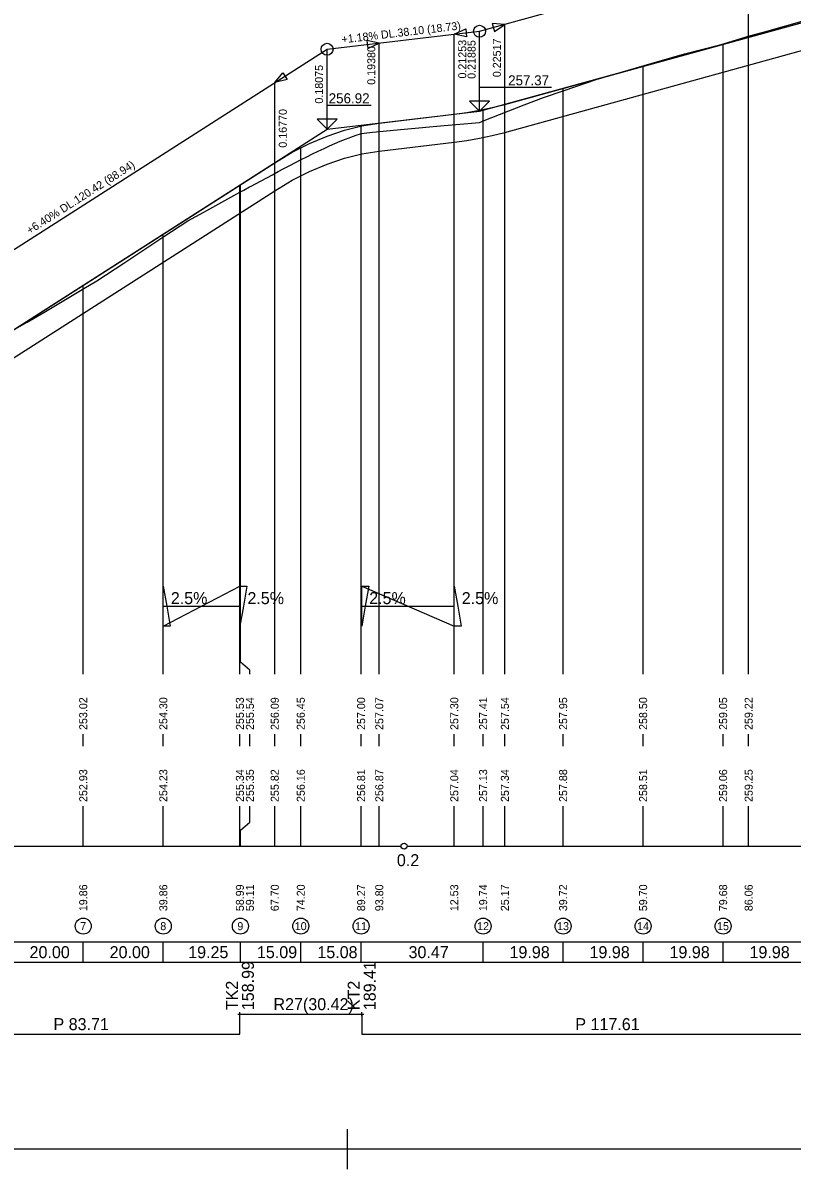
# Model space of a CAD drawing. Extents: x -5 to 681, y -26 to 404.
# Drawn here: x 174.8 to 366.9, y -25.7 to 260.8 of the extents above; entities that cross this region are included whole.
import ezdxf

# ---------------------------------------------------------------- set-up
doc = ezdxf.new("R2010")
doc.units = 0
for name, color, linetype in [('KOTA', 7, 'Continuous'), ('NOVY_STAV', 7, 'Continuous'), ('NS_OBLOUK', 7, 'Continuous'), ('PRIKOPY', 7, 'Continuous'), ('REZY_PO', 7, 'Continuous'), ('SESTAVY_REZU_PO', 7, 'Continuous'), ('SKLONOVE_POMERY', 7, 'Continuous'), ('SKLONOVE_POMERY_PROPOJENI', 7, 'Continuous'), ('SMEROVE_POMERY', 7, 'Continuous'), ('SMEROVE_POMERY_KOD', 7, 'Continuous'), ('SVK_STAT', 7, 'Continuous'), ('TABULKY', 7, 'Continuous'), ('ZNACKY', 7, 'Continuous')]:
    doc.layers.add(name, color=color, linetype=linetype)

msp = doc.modelspace()

# ---------------------------------------------------------------- linework, layer by layer
for p, q in [((255.78, -15.73), (255.78, -25.73)), ((255.78, -15.73), (255.78, -25.73)), ((255.78, -15.73), (255.78, -25.73)), ((255.78, -15.73), (255.78, -25.73)), ((255.78, -15.73), (255.78, -25.73)), ((255.78, -15.73), (255.78, -25.73)), ((255.78, -15.73), (255.78, -25.73)), ((255.78, -15.73), (255.78, -25.73)), ((255.78, -15.73), (255.78, -25.73)), ((255.78, -15.73), (255.78, -25.73)), ((255.78, -15.73), (255.78, -25.73)), ((255.78, -15.73), (255.78, -25.73)), ((255.78, -15.73), (255.78, -25.73)), ((255.78, -15.73), (255.78, -25.73)), ((255.78, -15.73), (255.78, -25.73)), ((255.78, -15.73), (255.78, -25.73)), ((255.78, -15.73), (255.78, -25.73)), ((255.78, -15.73), (255.78, -25.73)), ((255.78, -15.73), (255.78, -25.73)), ((255.78, -15.73), (255.78, -25.73)), ((260.78, -20.73), (250.78, -20.73)), ((260.78, -20.73), (250.78, -20.73)), ((260.78, -20.73), (250.78, -20.73)), ((260.78, -20.73), (250.78, -20.73)), ((260.78, -20.73), (250.78, -20.73)), ((260.78, -20.73), (250.78, -20.73)), ((260.78, -20.73), (250.78, -20.73)), ((260.78, -20.73), (250.78, -20.73)), ((260.78, -20.73), (250.78, -20.73)), ((260.78, -20.73), (250.78, -20.73)), ((260.78, -20.73), (250.78, -20.73)), ((260.78, -20.73), (250.78, -20.73)), ((260.78, -20.73), (250.78, -20.73)), ((260.78, -20.73), (250.78, -20.73)), ((260.78, -20.73), (250.78, -20.73)), ((260.78, -20.73), (250.78, -20.73)), ((260.78, -20.73), (250.78, -20.73)), ((260.78, -20.73), (250.78, -20.73)), ((260.78, -20.73), (250.78, -20.73)), ((260.78, -20.73), (250.78, -20.73))]:
    msp.add_line(p, q)
msp.add_lwpolyline([(675.78, -20.77), (0.45, -20.77), (0.45, 399.23), (675.78, 399.23)], close=True)
at = {"layer": 'KOTA'}
for points in [[(288.85, 241.2), (286.35, 241.2), (288.85, 238.7), (288.85, 244.7), (306.79, 244.7)], [(288.85, 238.7), (288.85, 238.7), (291.35, 241.2), (288.85, 241.2)], [(250.75, 236.71), (248.25, 236.71), (250.75, 234.21), (250.75, 240.21), (261.75, 240.21)], [(250.75, 234.21), (250.75, 234.21), (253.25, 236.71), (250.75, 236.71)]]:
    msp.add_lwpolyline(points, dxfattribs=at)
at = {"layer": 'NOVY_STAV'}
for points in [[(288.85, 258.7), (399.15, 289.13)], [(70, 163.01), (130.33, 157.15), (250.75, 234.21), (288.85, 238.7), (399.15, 269.13), (477.05, 273.02), (495.66, 261.13), (501.87, 260.18)], [(70, 163.01), (111.91, 158.94), (116.51, 158.71), (121.12, 158.9), (125.73, 159.51), (130.33, 160.55), (134.94, 162.01), (139.54, 163.9), (144.15, 166.21), (148.76, 168.94), (237.7, 225.86), (242.05, 228.45), (246.4, 230.67), (250.75, 232.5), (255.1, 233.96), (259.45, 235.04), (263.8, 235.75), (282.53, 237.95), (285.69, 238.39), (288.85, 238.95), (292.01, 239.63), (295.17, 240.44), (390.11, 266.64)], [(250.75, 254.21), (288.85, 258.7)], [(288.85, 238.7), (288.85, 258.7)], [(130.33, 177.15), (250.75, 254.21)], [(250.75, 234.21), (250.75, 254.21)]]:
    msp.add_lwpolyline(points, dxfattribs=at)
for centre in [(288.85, 258.7), (250.75, 254.21)]:
    msp.add_circle(centre, 1.5, dxfattribs=at)
at = {"layer": 'NS_OBLOUK'}
for points in [[(282.53, 257.95), (285.39, 259.3), (285.62, 257.31), (282.53, 257.95)], [(282.53, 237.95), (282.53, 257.95)], [(295.17, 260.44), (292.01, 260.61), (292.55, 258.68), (295.17, 260.44)], [(295.17, 240.44), (295.17, 260.44)], [(263.8, 255.75), (260.7, 256.39), (260.94, 254.4), (263.8, 255.75)], [(263.8, 235.75), (263.8, 255.75)], [(237.7, 245.86), (239.68, 248.32), (240.76, 246.63), (237.7, 245.86)], [(237.7, 225.86), (237.7, 245.86)]]:
    msp.add_lwpolyline(points, dxfattribs=at)
at = {"layer": 'PRIKOPY'}
msp.add_lwpolyline([(70, 156.01), (111.91, 151.94), (116.51, 151.71), (133.5, 151.72), (144.15, 159.21), (148.76, 161.94), (237.7, 218.86), (242.05, 221.45), (246.4, 223.67), (250.75, 225.5), (255.1, 226.96), (259.45, 228.04), (263.8, 228.75), (282.53, 230.95), (285.69, 231.39), (288.85, 231.95), (292.01, 232.63), (295.17, 233.44), (390.11, 259.64)], dxfattribs=at)
at = {"layer": 'REZY_PO'}
msp.add_lwpolyline([(170, 182.65), (175.85, 185.96), (180, 188.43), (190, 194.38), (193.22, 196.3), (200, 200.77), (210, 207.37), (216.02, 211.35), (220, 213.52), (228.99, 218.45), (229.5, 218.72), (230, 219), (231.43, 219.79), (231.82, 220.01), (232.86, 220.56), (234.29, 221.32), (235.71, 222.09), (237.14, 222.85), (238.57, 223.62), (240, 224.38), (241.43, 225.13), (242.86, 225.88), (244.29, 226.62), (245.71, 227.34), (247.14, 228.05), (248.57, 228.74), (250, 229.41), (251.34, 230.03), (252.69, 230.62), (254.03, 231.2), (255.38, 231.75), (256.29, 232.11), (256.72, 232.27), (258.06, 232.74), (259.11, 233.08), (259.41, 233.13), (260, 233.21), (262.09, 233.49), (270, 234.21), (280, 235.13), (288.84, 235.93), (290, 236.38), (300, 240.28), (304.83, 242.15), (310, 243.92), (318.01, 246.66), (320, 247.24), (330, 250.15), (340, 253.06), (340.06, 253.08), (348.82, 255.3), (350, 255.65), (356.27, 257.55), (360, 258.59), (370, 261.4)], dxfattribs=at)
at = {"layer": 'SESTAVY_REZU_PO'}
for points in [[(170.75, 55), (269.25, 55)], [(270.75, 55), (369.25, 55)], [(189.86, 26), (189.86, 31)], [(209.86, 26), (209.86, 31)], [(229.11, 26), (229.11, 31)], [(244.2, 26), (244.2, 31)], [(259.27, 26), (259.27, 31)], [(289.74, 26), (289.74, 31)], [(309.72, 26), (309.72, 31)], [(329.7, 26), (329.7, 31)], [(349.68, 26), (349.68, 31)]]:
    msp.add_lwpolyline(points, dxfattribs=at)
msp.add_circle((270, 55), 0.75, dxfattribs=at)
at = {"layer": 'SKLONOVE_POMERY'}
for points in [[(209.86, 110), (209.86, 120), (209.86, 120), (210.74, 115), (211.61, 110), (209.86, 110)], [(228.99, 110), (228.99, 120), (230.74, 120), (229.87, 115), (228.99, 110), (228.99, 110)], [(259.41, 110), (259.41, 120), (261.16, 120), (260.28, 115), (259.41, 110), (259.41, 110)], [(282.53, 110), (282.53, 120), (282.53, 120), (283.4, 115), (284.28, 110), (282.53, 110)]]:
    msp.add_lwpolyline(points, dxfattribs=at)
at = {"layer": 'SKLONOVE_POMERY_PROPOJENI'}
for points in [[(209.86, 110), (228.99, 120)], [(259.41, 120), (282.53, 110)], [(209.86, 115), (228.99, 115)], [(259.41, 115), (282.53, 115)]]:
    msp.add_lwpolyline(points, dxfattribs=at)
at = {"layer": 'SMEROVE_POMERY'}
msp.add_lwpolyline([(70, 8), (107.63, 8), (107.63, 3), (107.63, 8), (107.63, 3), (145.28, 3), (145.28, 8), (145.28, 3), (145.28, 8), (228.99, 8), (228.99, 13), (259.41, 13), (259.41, 8), (377.02, 8)], dxfattribs=at)
at = {"layer": 'SMEROVE_POMERY_KOD'}
for points in [[(228.49, 13), (229.49, 13)], [(228.99, 12.5), (228.99, 13.5)], [(258.91, 13), (259.91, 13)], [(259.41, 12.5), (259.41, 13.5)]]:
    msp.add_lwpolyline(points, dxfattribs=at)
at = {"layer": 'SVK_STAT'}
for points in [[(349.68, 98), (349.68, 255.56)], [(356.06, 98), (356.06, 257.49)], [(329.7, 98), (329.7, 250.06)], [(309.72, 98), (309.72, 244.46)], [(282.53, 98), (282.53, 237.95)], [(289.74, 98), (289.74, 239.14)], [(295.17, 98), (295.17, 240.44)], [(259.27, 98), (259.27, 235)], [(263.8, 98), (263.8, 235.75)], [(244.2, 98), (244.2, 229.55)], [(237.7, 98), (237.7, 225.86)], [(228.99, 98), (228.99, 220.29)], [(231.49, 98), (231.49, 99), (229.11, 101), (229.11, 220.36)], [(209.86, 98), (209.86, 208.04)], [(189.86, 98), (189.86, 195.25)], [(189.86, 80), (189.86, 83)], [(209.86, 80), (209.86, 83)], [(228.99, 80), (228.99, 83)], [(231.49, 80), (231.49, 83)], [(237.7, 80), (237.7, 83)], [(244.2, 80), (244.2, 83)], [(259.27, 80), (259.27, 83)], [(263.8, 80), (263.8, 83)], [(282.53, 80), (282.53, 83)], [(289.74, 80), (289.74, 83)], [(295.17, 80), (295.17, 83)], [(309.72, 80), (309.72, 83)], [(329.7, 80), (329.7, 83)], [(349.68, 80), (349.68, 83)], [(356.06, 80), (356.06, 83)], [(189.86, 55), (189.86, 65)], [(209.86, 55), (209.86, 65)], [(228.99, 55), (228.99, 65)], [(229.11, 55), (229.11, 59), (231.49, 61), (231.49, 65)], [(237.7, 55), (237.7, 65)], [(244.2, 55), (244.2, 65)], [(259.27, 55), (259.27, 65)], [(263.8, 55), (263.8, 65)], [(282.53, 55), (282.53, 65)], [(289.74, 55), (289.74, 65)], [(295.17, 55), (295.17, 65)], [(309.72, 55), (309.72, 65)], [(329.7, 55), (329.7, 65)], [(349.68, 55), (349.68, 65)], [(356.06, 55), (356.06, 65)]]:
    msp.add_lwpolyline(points, dxfattribs=at)
for centre in [(189.86, 35), (209.86, 35), (229.11, 35), (244.2, 35), (259.27, 35), (289.74, 35), (309.72, 35), (329.7, 35), (349.68, 35)]:
    msp.add_circle(centre, 2, dxfattribs=at)
at = {"layer": 'TABULKY'}
msp.add_lwpolyline([(70, 26), (501.87, 26), (501.87, 31), (70, 31), (70, 26)], dxfattribs=at)
at = {"layer": 'ZNACKY'}
msp.add_lwpolyline([(356.06, 257.24), (356.06, 289.66), (352.06, 287.66), (356.06, 285.66)], dxfattribs=at)

# ---------------------------------------------------------------- texts
at = {"layer": 'KOTA'}
for s, p in [('257.37', (295.99, 245.2)), ('256.92', (251.16, 240.71))]:
    msp.add_text(s, height=2.5, dxfattribs=at).set_placement(p)
at = {"layer": 'NOVY_STAV'}
for s, rotation, p in [('+1.18% DL.38.10 (18.73)', 6.7206, (254.51, 255.66)), (' 0.21885', 90, (287.85, 246.07)), (' 0.18075', 90, (249.75, 239.88)), ('+6.40% DL.120.42 (88.94)', 32.6153, (176.5, 207.88))]:
    msp.add_text(s, height=2, rotation=rotation, dxfattribs=at).set_placement(p)
at = {"layer": 'NS_OBLOUK'}
for s, p in [(' 0.21253', (285.53, 246.15)), (' 0.22517', (294.17, 246.49)), (' 0.19380', (262.8, 244.59)), (' 0.16770', (240.7, 228.86))]:
    msp.add_text(s, height=2, rotation=90, dxfattribs=at).set_placement(p)
at = {"layer": 'SESTAVY_REZU_PO'}
for s, p in [('0.2', (268.2, 50)), ('20.00', (176.46, 27)), ('20.00', (196.46, 27)), ('19.25', (216.08, 27)), ('15.09', (233.25, 27)), ('15.08', (248.34, 27)), ('30.47', (271.11, 27)), ('19.98', (296.33, 27)), ('19.98', (316.31, 27)), ('19.98', (336.29, 27)), ('19.98', (356.27, 27))]:
    msp.add_text(s, height=3, dxfattribs=at).set_placement(p)
at = {"layer": 'SKLONOVE_POMERY'}
for p in [(211.74, 115.5), (230.87, 115.5), (261.28, 115.5), (284.4, 115.5)]:
    msp.add_text('2.5%', height=3, dxfattribs=at).set_placement(p)
at = {"layer": 'SMEROVE_POMERY'}
for s, p in [('R27(30.42)', (237.38, 14)), ('P 83.71', (182.44, 9)), ('P 117.61', (312.77, 9))]:
    msp.add_text(s, height=3, dxfattribs=at).set_placement(p)
at = {"layer": 'SMEROVE_POMERY_KOD'}
for s, p in [('158.99', (232.49, 14)), ('189.41', (262.91, 14)), ('TK2', (228.49, 14)), ('KT2', (258.91, 14))]:
    msp.add_text(s, height=3, rotation=90, dxfattribs=at).set_placement(p)
at = {"layer": 'SVK_STAT'}
for s, p in [(' 253.02', (190.86, 83.3)), (' 254.30', (210.86, 83.3)), (' 255.53', (229.99, 83.3)), (' 255.54', (232.49, 83.3)), (' 256.09', (238.7, 83.3)), (' 256.45', (245.2, 83.3)), (' 257.00', (260.27, 83.3)), (' 257.07', (264.8, 83.3)), (' 257.30', (283.53, 83.3)), (' 257.41', (290.74, 83.3)), (' 257.54', (296.17, 83.3)), (' 257.95', (310.72, 83.3)), (' 258.50', (330.7, 83.3)), (' 259.05', (350.68, 83.3)), (' 259.22', (357.06, 83.3)), (' 252.93', (190.86, 65.3)), (' 254.23', (210.86, 65.3)), (' 255.34', (229.99, 65.3)), (' 255.35', (232.49, 65.3)), (' 255.82', (238.7, 65.3)), (' 256.16', (245.2, 65.3)), (' 256.81', (260.27, 65.3)), (' 256.87', (264.8, 65.3)), (' 257.04', (283.53, 65.3)), (' 257.13', (290.74, 65.3)), (' 257.34', (296.17, 65.3)), (' 257.88', (310.72, 65.3)), (' 258.51', (330.7, 65.3)), (' 259.06', (350.68, 65.3)), (' 259.25', (357.06, 65.3)), (' 19.86', (190.86, 38)), (' 39.86', (210.86, 38)), (' 58.99', (229.99, 38)), (' 59.11', (232.49, 38)), (' 67.70', (238.7, 38)), (' 74.20', (245.2, 38)), (' 89.27', (260.27, 38)), (' 93.80', (264.8, 38)), (' 12.53', (283.53, 38)), (' 19.74', (290.74, 38)), (' 25.17', (296.17, 38)), (' 39.72', (310.72, 38)), (' 59.70', (330.7, 38)), (' 79.68', (350.68, 38)), (' 86.06', (357.06, 38))]:
    msp.add_text(s, height=2, rotation=90, dxfattribs=at).set_placement(p)
for s, p in [('7', (189.11, 34)), ('8', (209.11, 34)), ('9', (228.35, 34)), ('10', (242.69, 34)), ('11', (257.77, 34)), ('12', (288.23, 34)), ('13', (308.21, 34)), ('14', (328.19, 34)), ('15', (348.17, 34))]:
    msp.add_text(s, height=2, dxfattribs=at).set_placement(p)

doc.saveas('drawing.dxf')
